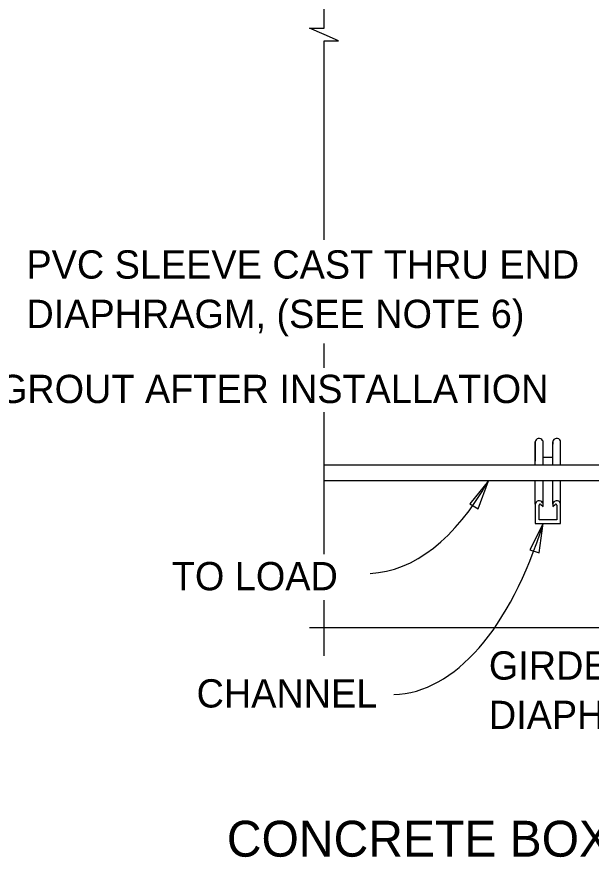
# Model space of a CAD drawing. Extents: x -1660015.2 to -1659984.9, y 2580594.2 to 2580616.7.
# Drawn here: x -1659995.935 to -1659992.865, y 2580606.68 to 2580611.174 of the extents above; entities that cross this region are included whole.
import ezdxf

# ---------------------------------------------------------------- set-up
doc = ezdxf.new("R2010")
doc.units = 0
for name, color, linetype in [('Default', 7, 'Continuous'), ('PlotBorder_dp', 7, 'Continuous'), ('SheetLines_dp', 7, 'Continuous')]:
    doc.layers.add(name, color=color, linetype=linetype)

msp = doc.modelspace()

# ---------------------------------------------------------------- linework, layer by layer
at = {"layer": 'Default'}
for p, q in [((-1659993.1636, 2580608.7761), (-1659993.1636, 2580608.9011)), ((-1659993.1636, 2580608.9011), (-1659993.1636, 2580608.7985)), ((-1659993.122, 2580608.9054), (-1659993.1241, 2580608.9093)), ((-1659993.122, 2580608.8894), (-1659993.122, 2580608.9054)), ((-1659993.122, 2580608.7761), (-1659993.122, 2580608.9011)), ((-1659993.0676, 2580608.9093), (-1659993.0698, 2580608.9054)), ((-1659993.0698, 2580608.9054), (-1659993.0698, 2580608.8894)), ((-1659993.0698, 2580608.7761), (-1659993.0698, 2580608.9011)), ((-1659993.0282, 2580608.7761), (-1659993.0282, 2580608.9011)), ((-1659993.0698, 2580608.8171), (-1659993.122, 2580608.8171)), ((-1659990.1046, 2580608.776), (-1659994.2928, 2580608.776)), ((-1659990.1046, 2580608.6927), (-1659994.2928, 2580608.6927)), ((-1659993.1636, 2580608.5677), (-1659993.1636, 2580608.6927)), ((-1659993.122, 2580608.5677), (-1659993.122, 2580608.6927)), ((-1659993.0698, 2580608.5677), (-1659993.0698, 2580608.6927)), ((-1659993.0282, 2580608.5677), (-1659993.0282, 2580608.6927)), ((-1659993.122, 2580608.5721), (-1659993.1241, 2580608.5759)), ((-1659993.0676, 2580608.5759), (-1659993.0698, 2580608.5721)), ((-1659993.1636, 2580608.5677), (-1659993.1636, 2580608.4651)), ((-1659993.1428, 2580608.4838), (-1659993.1428, 2580608.5634)), ((-1659993.1339, 2580608.5667), (-1659993.122, 2580608.556)), ((-1659993.122, 2580608.556), (-1659993.122, 2580608.5721)), ((-1659993.0698, 2580608.5721), (-1659993.0698, 2580608.556)), ((-1659993.0698, 2580608.556), (-1659993.0579, 2580608.5667)), ((-1659993.049, 2580608.5634), (-1659993.049, 2580608.4838)), ((-1659993.0282, 2580608.4651), (-1659993.0282, 2580608.5677)), ((-1659993.1636, 2580608.4651), (-1659993.0282, 2580608.4651)), ((-1659993.049, 2580608.4838), (-1659993.1428, 2580608.4838))]:
    msp.add_line(p, q, dxfattribs=at)
for centre, major_axis, start_param, end_param in [((-1659993.1428, 2580608.9011), (-0.0208, 0), 3.598509, 6.283184), ((-1659993.049, 2580608.9011), (0.0208, 0), 0.000002, 2.684677), ((-1659993.1428, 2580608.5677), (-0.0208, 0), 3.598509, 6.283184), ((-1659993.049, 2580608.5677), (0.0208, 0), 0.000002, 2.684677), ((-1659993.1376, 2580608.5634), (-0.0052, 0), 3.926991, 6.283185), ((-1659993.0542, 2580608.5634), (0.0052, 0), 6.283185, 8.63938)]:
    msp.add_ellipse(centre, major_axis=major_axis, ratio=0.8951, start_param=start_param, end_param=end_param, dxfattribs=at)
at = {"layer": 'SheetLines_dp'}
for points in [[(-1659994.2928, 2580609.9808), (-1659994.2928, 2580611.0451), (-1659994.2153, 2580611.0451), (-1659994.2928, 2580611.0789), (-1659994.3703, 2580611.1126), (-1659994.2928, 2580611.1126), (-1659994.2928, 2580614.289)], [(-1659994.2928, 2580609.297), (-1659994.2928, 2580609.4277)], [(-1659994.2928, 2580608.3007), (-1659994.2928, 2580609.0597)], [(-1659994.2928, 2580607.7573), (-1659994.2928, 2580608.0549)], [(-1659986.5682, 2580607.9066), (-1659989.8898, 2580607.9066), (-1659989.8898, 2580607.9841), (-1659989.9235, 2580607.9066), (-1659989.9573, 2580607.8291), (-1659989.9573, 2580607.9066), (-1659994.3703, 2580607.9066)]]:
    msp.add_lwpolyline(points, dxfattribs=at)
for points in [[(-1659993.4145, 2580608.6927), (-1659993.5143, 2580608.5697), (-1659993.4682, 2580608.5437)], [(-1659993.1214, 2580608.4651), (-1659993.1931, 2580608.3239), (-1659993.1426, 2580608.3081)]]:
    msp.add_lwpolyline(points, close=True, dxfattribs=at)
for centre, major_axis, ratio, start_param, end_param in [((-1659994.1575, 2580610.5655), (-0.1111, 2.3674), 0.464296, 3.141604, 3.778402), ((-1659993.9947, 2580609.7563), (-0.0751, 2.2066), 0.468341, 3.141584, 4.071496)]:
    msp.add_ellipse(centre, major_axis=major_axis, ratio=ratio, start_param=start_param, end_param=end_param, dxfattribs=at)

# ---------------------------------------------------------------- texts
at = {"layer": 'PlotBorder_dp'}
for s, height, p in [('GROUT AFTER INSTALLATION', 0.1512, (-1659996.0365, 2580609.1088)), ('TO LOAD', 0.1512, (-1659995.1067, 2580608.1077)), ('CHANNEL', 0.1512, (-1659994.9744, 2580607.4808)), ('CONCRETE BOX GIRDER BRIDGE SECTION THRU END BENTS', 0.192, (-1659994.8125, 2580606.6832))]:
    msp.add_text(s, height=height, dxfattribs=at).set_placement(p)
at = {"layer": 'SheetLines_dp'}
for s, p in [('PVC SLEEVE CAST THRU END ', (-1659995.884, 2580609.7742)), ('DIAPHRAGM, (SEE NOTE 6)', (-1659995.884, 2580609.5102)), ('GIRDER END', (-1659993.4117, 2580607.6299)), ('DIAPHRAGM', (-1659993.4117, 2580607.3659))]:
    msp.add_text(s, height=0.1512, dxfattribs=at).set_placement(p)

doc.saveas('drawing.dxf')
